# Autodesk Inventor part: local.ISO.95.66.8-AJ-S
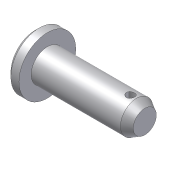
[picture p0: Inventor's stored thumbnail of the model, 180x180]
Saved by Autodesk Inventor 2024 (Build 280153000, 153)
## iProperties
Company: ATC
Created: 2023-03
Part Number: local.ISO.95.66.8-AJ-S
Material: Standard
Description: Sworzeń
Vendor: Autodesk Inc.
Document SubType Name: Modeling
Standard: ISO 2341
Designer: Andrzej Jaskulski
Size Designation: B - 8 x 24
Density: 1 g/cm^3
Appearance: Domyślna
Checked By: A.J.
Engr Approved By: Andrzej Jaskulski
Mfg Approved By: Andrzej Jaskulski
Authority: A.J.
_DisabledCommands: 0
Author: Andrzej Jaskulski
Revision Number: 1/24
Title: A.J.: Kurs R2024-MEP
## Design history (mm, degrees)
revolve "Bryła" stored, may be unused: angle "d4" = 90 deg
sketch "Szkic1"
  geometry: L1 (-3, 0)-(-3, 7); L2 (-3, 7)-(0, 7); L3 (0, 7)-(0, 4); L4 (0, 4)-(24, 4); L5 (24, 4)-(24, 0); L6 (-3, 0)-(24, 0); L7 (-8.4, 0)-(29.4, 0) reference; L8 (0, -2.6)-(0, 8.6) reference; C1 r 1 at (20.5, 0)
  constraints: 12 end point, 3 parallel, 2 collinear, 2 perpendicular, 1 centre point, 1 point on line, 1 vertical
  dimensions: "d0" = 8 diameter of L4 L6 (= NND); "d1" = 14 diameter of L2 L6 (= KOD); "d2" = 3 distance of L1.end L2.end (= KOH); "d3" = 24 distance of L3.end L4.end (= NLG); "d5" = 3.5 distance from line of L5 C1.centre (= DIST); "d6" = 2 diameter of C1 (= BOR)
extrude "Otwór" cut sketch "Szkic1" extent not by distance; stored distance "d7" = 8 (= NND); taper "d8" = 0 deg
node "Bryła1"
node "Korpusy bryłowe"
node "Korpusy powierzchniowe"
chamfer "Faza1" distance "d9" = 1 (= PHH2); stored, may be unused: angle "d10" = 45 deg (= FAWI2), second distance "d16" = 1 (= PHH2)
chamfer "Faza2" distance "d11" = 2 (= PHH1); stored, may be unused: angle "d12" = 30 deg (= FAWI1), second distance "d17" = 2 (= PHH1)
other parameters: "PHH1" = 2 [user parameter; used in 2 equation terms], "PHH2" = 1 [user parameter; used in 2 equation terms], "KOD" = 14 [user parameter; used in 1 equation term], "KOH" = 3 [user parameter; used in 1 equation term], "NND" = 8 [user parameter; used in 2 equation terms], "FAWI1" = 30 deg [user parameter; used in 1 equation term], "FAWI2" = 45 deg [user parameter; used in 1 equation term], "DIST" = 3.5 [user parameter; used in 1 equation term], "BOR" = 2 [user parameter; used in 1 equation term], "NLG" = 24 [user parameter; used in 1 equation term], "d13" = 0, "d14" = 0
